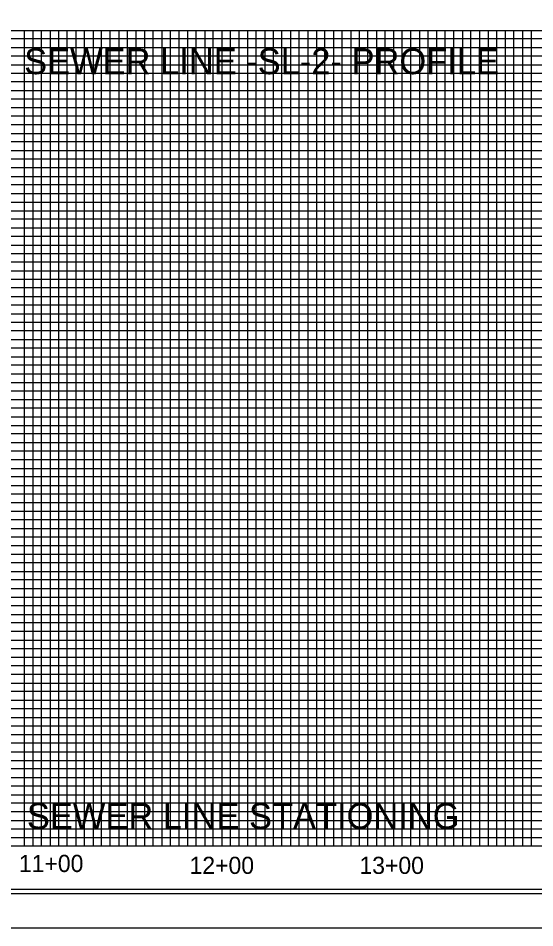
# Model space of a CAD drawing. Extents: x 0 to 2694, y -754 to 1499.
# Drawn here: x 1.849 to 2.35, y 0.008 to 0.891 of the extents above; entities that cross this region are included whole.
import ezdxf

# ---------------------------------------------------------------- set-up
doc = ezdxf.new("R2010")
doc.units = 0
for name, color, linetype in [('Sewer Line Text and Text Box and Leader Line (B1)', 7, 'Continuous'), ('Sheet Profile Grid Major CELL', 7, 'Continuous'), ('Sheet Profile Grid Middle', 7, 'Continuous'), ('Sheet Profile Grid Minor CELL', 7, 'Continuous'), ('UC Plan Profile Sheet 34 CELL', 7, 'Continuous')]:
    doc.layers.add(name, color=color, linetype=linetype)

msp = doc.modelspace()

# ---------------------------------------------------------------- linework, layer by layer
at = {"layer": 'Sheet Profile Grid Major CELL'}
for points in [[(0.30499, 0.87916), (2.59666, 0.87916)], [(1.88833, 0.0875), (1.88833, 0.87916), (1.97166, 0.87916), (1.97166, 0.0875)], [(2.05499, 0.0875), (2.05499, 0.87916), (2.13833, 0.87916), (2.13833, 0.0875)], [(2.22166, 0.0875), (2.22166, 0.87916), (2.30499, 0.87916), (2.30499, 0.0875)], [(2.80499, 0.79583), (0.30499, 0.79583), (0.30499, 0.7125), (2.80499, 0.7125)], [(2.80499, 0.62916), (0.30499, 0.62916), (0.30499, 0.54583), (2.80499, 0.54583)], [(2.80499, 0.4625), (0.30499, 0.4625), (0.30499, 0.37916), (2.80499, 0.37916)], [(2.80499, 0.29583), (0.30499, 0.29583), (0.30499, 0.2125), (2.80499, 0.2125)], [(2.80499, 0.12916), (0.30499, 0.12916)]]:
    msp.add_lwpolyline(points, dxfattribs=at)
at = {"layer": 'Sheet Profile Grid Middle'}
for p, q in [((0.30499, 0.8375), (2.59666, 0.8375)), ((2.80499, 0.75416), (0.30499, 0.75416)), ((0.30499, 0.67083), (2.80499, 0.67083)), ((2.80499, 0.5875), (0.30499, 0.5875)), ((0.30499, 0.50416), (2.80499, 0.50416)), ((2.80499, 0.42083), (0.30499, 0.42083)), ((0.30499, 0.3375), (2.80499, 0.3375)), ((2.80499, 0.25416), (0.30499, 0.25416)), ((0.30499, 0.17083), (2.80499, 0.17083))]:
    msp.add_line(p, q, dxfattribs=at)
for points in [[(1.92999, 0.0875), (1.92999, 0.87916), (2.01333, 0.87916), (2.01333, 0.0875)], [(2.09666, 0.0875), (2.09666, 0.87916), (2.17999, 0.87916), (2.17999, 0.0875)], [(2.26333, 0.0875), (2.26333, 0.87916), (2.34666, 0.87916), (2.34666, 0.0875)]]:
    msp.add_lwpolyline(points, dxfattribs=at)
at = {"layer": 'Sheet Profile Grid Minor CELL'}
for points in [[(1.85499, 0.0875), (1.85499, 0.87916), (1.86333, 0.87916), (1.86333, 0.0875)], [(1.87166, 0.0875), (1.87166, 0.87916), (1.87999, 0.87916), (1.87999, 0.0875)], [(1.89666, 0.0875), (1.89666, 0.87916), (1.90499, 0.87916), (1.90499, 0.0875)], [(1.91333, 0.0875), (1.91333, 0.87916), (1.92166, 0.87916), (1.92166, 0.0875)], [(1.93833, 0.0875), (1.93833, 0.87916), (1.94666, 0.87916), (1.94666, 0.0875)], [(1.95499, 0.0875), (1.95499, 0.87916), (1.96333, 0.87916), (1.96333, 0.0875)], [(1.97999, 0.0875), (1.97999, 0.87916), (1.98833, 0.87916), (1.98833, 0.0875)], [(1.99666, 0.0875), (1.99666, 0.87916), (2.00499, 0.87916), (2.00499, 0.0875)], [(2.02166, 0.0875), (2.02166, 0.87916), (2.02999, 0.87916), (2.02999, 0.0875)], [(2.03833, 0.0875), (2.03833, 0.87916), (2.04666, 0.87916), (2.04666, 0.0875)], [(2.06333, 0.0875), (2.06333, 0.87916), (2.07166, 0.87916), (2.07166, 0.0875)], [(2.07999, 0.0875), (2.07999, 0.87916), (2.08833, 0.87916), (2.08833, 0.0875)], [(2.10499, 0.0875), (2.10499, 0.87916), (2.11333, 0.87916), (2.11333, 0.0875)], [(2.12166, 0.0875), (2.12166, 0.87916), (2.12999, 0.87916), (2.12999, 0.0875)], [(2.14666, 0.0875), (2.14666, 0.87916), (2.15499, 0.87916), (2.15499, 0.0875)], [(2.16333, 0.0875), (2.16333, 0.87916), (2.17166, 0.87916), (2.17166, 0.0875)], [(2.18833, 0.0875), (2.18833, 0.87916), (2.19666, 0.87916), (2.19666, 0.0875)], [(2.20499, 0.0875), (2.20499, 0.87916), (2.21333, 0.87916), (2.21333, 0.0875)], [(2.22999, 0.0875), (2.22999, 0.87916), (2.23833, 0.87916), (2.23833, 0.0875)], [(2.24666, 0.0875), (2.24666, 0.87916), (2.25499, 0.87916), (2.25499, 0.0875)], [(2.27166, 0.0875), (2.27166, 0.87916), (2.27999, 0.87916), (2.27999, 0.0875)], [(2.28833, 0.0875), (2.28833, 0.87916), (2.29666, 0.87916), (2.29666, 0.0875)], [(2.31333, 0.0875), (2.31333, 0.87916), (2.32166, 0.87916), (2.32166, 0.0875)], [(2.32999, 0.0875), (2.32999, 0.87916), (2.33833, 0.87916), (2.33833, 0.0875)], [(0.38833, 0.8625), (2.59666, 0.8625), (2.59666, 0.87083), (0.38833, 0.87083)], [(0.38833, 0.84583), (2.59666, 0.84583), (2.59666, 0.85416), (0.38833, 0.85416)], [(0.38833, 0.82083), (2.59666, 0.82083), (2.59666, 0.82916), (0.38833, 0.82916)], [(0.38833, 0.80416), (2.59666, 0.80416), (2.59666, 0.8125), (0.38833, 0.8125)], [(0.38833, 0.77916), (2.72166, 0.77916), (2.72166, 0.7875), (0.38833, 0.7875)], [(0.38833, 0.7625), (2.72166, 0.7625), (2.72166, 0.77083), (0.38833, 0.77083)], [(0.38833, 0.7375), (2.72166, 0.7375), (2.72166, 0.74583), (0.38833, 0.74583)], [(0.38833, 0.72083), (2.72166, 0.72083), (2.72166, 0.72916), (0.38833, 0.72916)], [(0.38833, 0.70416), (2.72166, 0.70416)], [(0.38833, 0.6875), (2.72166, 0.6875), (2.72166, 0.69583), (0.38833, 0.69583)], [(0.38833, 0.6625), (2.72166, 0.6625), (2.72166, 0.67916), (0.38833, 0.67916)], [(0.38833, 0.64583), (2.72166, 0.64583), (2.72166, 0.65416), (0.38833, 0.65416)], [(0.38833, 0.62083), (2.72166, 0.62083), (2.72166, 0.6375), (0.38833, 0.6375)], [(0.38833, 0.60416), (2.72166, 0.60416), (2.72166, 0.6125), (0.38833, 0.6125)], [(0.38833, 0.57916), (2.72166, 0.57916), (2.72166, 0.59583), (0.38833, 0.59583)], [(0.38833, 0.5625), (2.72166, 0.5625), (2.72166, 0.57083), (0.38833, 0.57083)], [(0.38833, 0.5375), (2.72166, 0.5375), (2.72166, 0.55416), (0.38833, 0.55416)], [(0.38833, 0.52083), (2.72166, 0.52083), (2.72166, 0.52916), (0.38833, 0.52916)], [(0.38833, 0.49583), (2.72166, 0.49583), (2.72166, 0.5125), (0.38833, 0.5125)], [(0.38833, 0.47916), (2.72166, 0.47916), (2.72166, 0.4875), (0.38833, 0.4875)], [(0.38833, 0.45416), (2.72166, 0.45416), (2.72166, 0.47083), (0.38833, 0.47083)], [(0.38833, 0.4375), (2.72166, 0.4375), (2.72166, 0.44583), (0.38833, 0.44583)], [(0.38833, 0.4125), (2.72166, 0.4125), (2.72166, 0.42916), (0.38833, 0.42916)], [(0.38833, 0.39583), (2.72166, 0.39583), (2.72166, 0.40416), (0.38833, 0.40416)], [(0.38833, 0.37083), (2.72166, 0.37083), (2.72166, 0.3875), (0.38833, 0.3875)], [(0.38833, 0.35416), (2.72166, 0.35416), (2.72166, 0.3625), (0.38833, 0.3625)], [(0.38833, 0.32916), (2.72166, 0.32916), (2.72166, 0.34583), (0.38833, 0.34583)], [(0.38833, 0.3125), (2.72166, 0.3125), (2.72166, 0.32083), (0.38833, 0.32083)], [(0.38833, 0.2875), (2.72166, 0.2875), (2.72166, 0.30416), (0.38833, 0.30416)], [(0.38833, 0.27083), (2.72166, 0.27083), (2.72166, 0.27916), (0.38833, 0.27916)], [(0.38833, 0.24583), (2.72166, 0.24583), (2.72166, 0.2625), (0.38833, 0.2625)], [(0.38833, 0.22916), (2.72166, 0.22916), (2.72166, 0.2375), (0.38833, 0.2375)], [(0.38833, 0.20416), (2.72166, 0.20416), (2.72166, 0.22083), (0.38833, 0.22083)], [(0.38833, 0.09583), (2.72166, 0.09583), (2.72166, 0.10416), (0.38833, 0.10416), (0.38833, 0.1125), (2.72166, 0.1125), (2.72166, 0.12083), (0.38833, 0.12083), (0.38833, 0.12916), (0.38833, 0.1375), (2.72166, 0.1375), (2.72166, 0.14583), (0.38833, 0.14583), (0.38833, 0.15416), (2.72166, 0.15416), (2.72166, 0.1625), (0.38833, 0.1625), (0.38833, 0.17083), (0.38833, 0.17916), (2.72166, 0.17916), (2.72166, 0.1875), (0.38833, 0.1875), (0.38833, 0.19583), (2.72166, 0.19583)]]:
    msp.add_lwpolyline(points, dxfattribs=at)
at = {"layer": 'UC Plan Profile Sheet 34 CELL'}
msp.add_line((2.80499, 0.0875), (0.30499, 0.0875), dxfattribs=at)
for points in [[(0.02749, 0.00833), (2.83333, 0.00833), (2.83333, 1.83333), (0.02749, 1.83333)], [(0.04916, 0.04166), (2.82583, 0.04166), (2.82583, 1.8), (0.04916, 1.8)], [(2.80499, 1.79583), (0.30499, 1.79583), (0.30499, 0.04583), (2.80499, 0.04583)], [(0.38833, 0.87916), (2.59666, 0.87916), (2.59666, 0.79583), (2.72166, 0.79583), (2.72166, 0.0875), (0.38833, 0.0875)]]:
    msp.add_lwpolyline(points, close=True, dxfattribs=at)

# ---------------------------------------------------------------- texts
at = {"layer": 'Sewer Line Text and Text Box and Leader Line (B1)'}
for s, p in [('SEWER LINE -SL-2- PROFILE', (1.85482, 0.83663)), ('SEWER LINE STATIONING', (1.85746, 0.10431))]:
    msp.add_text(s, height=0.025, dxfattribs=at).set_placement(p)
at = {"layer": 'UC Plan Profile Sheet 34 CELL'}
for s, p in [('11+00', (1.84971, 0.06245)), ('12+00', (2.01528, 0.06061)), ('13+00', (2.18012, 0.06061))]:
    msp.add_text(s, height=0.016667, dxfattribs=at).set_placement(p)

doc.saveas('drawing.dxf')
